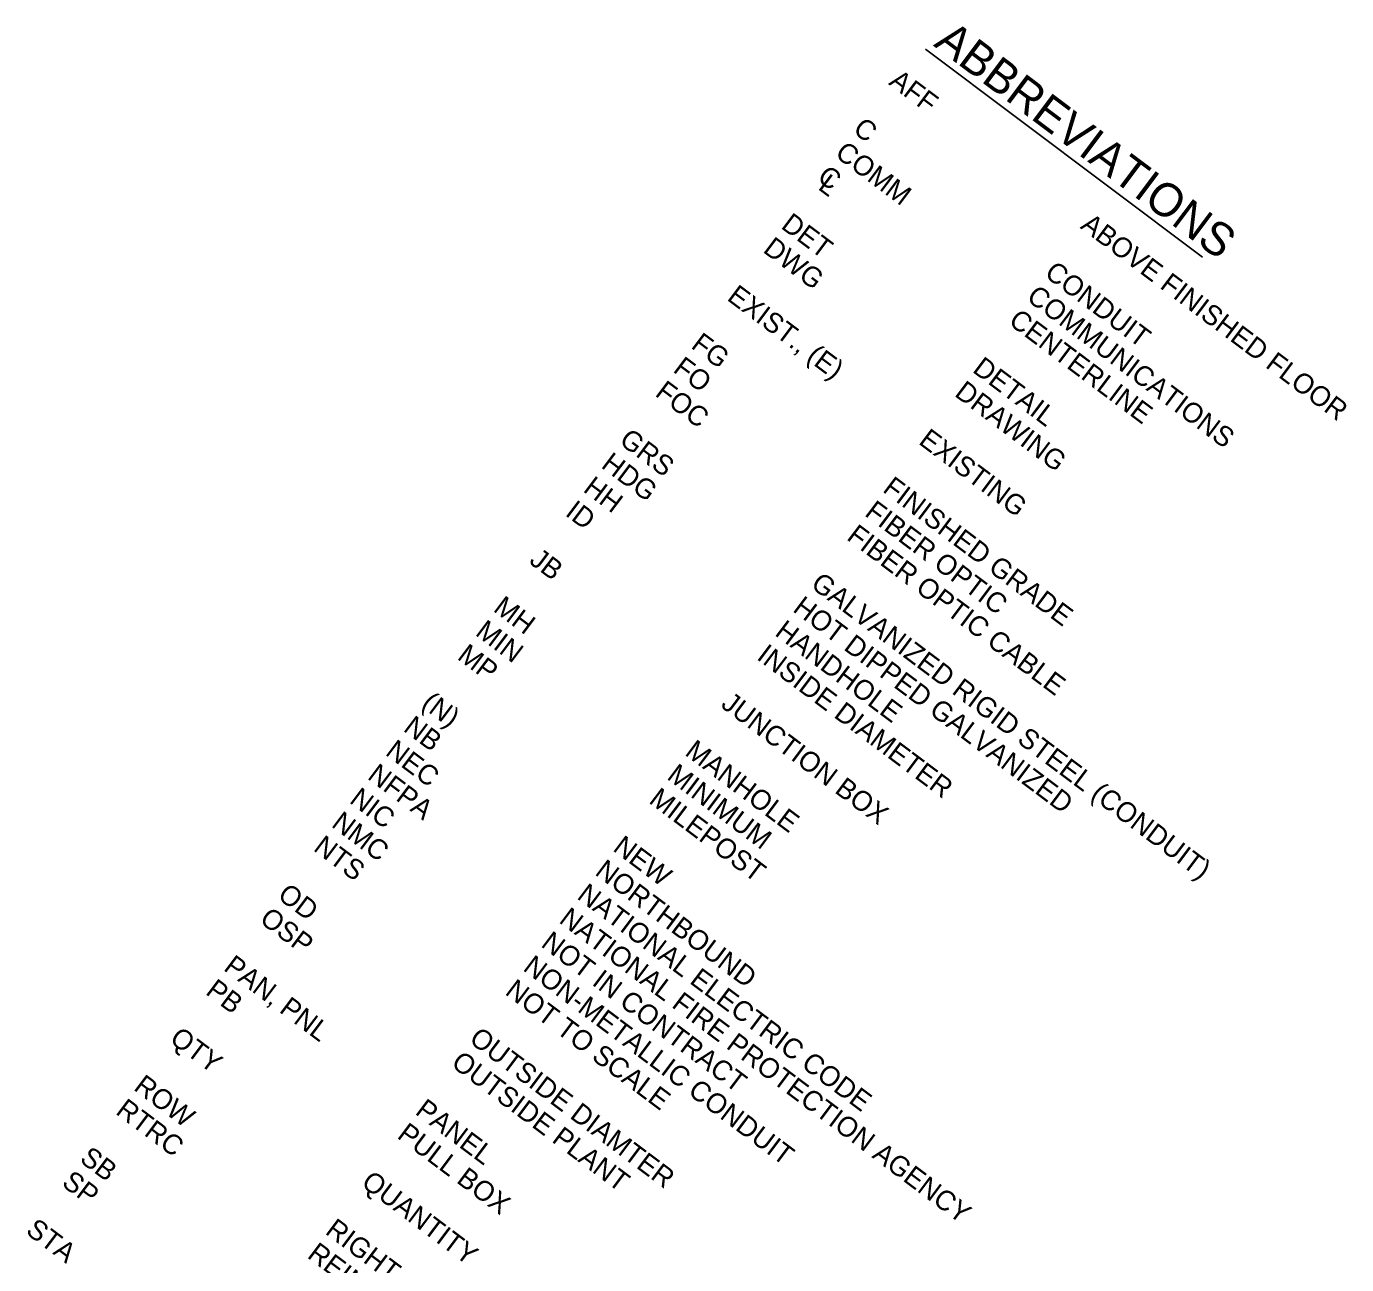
# Model space of a CAD drawing. Extents: x 626494 to 629419, y 365986 to 369334.
# Drawn here: x 628015.6 to 628253.6, y 368612.5 to 368835.9 of the extents above; entities that cross this region are included whole.
import ezdxf

# ---------------------------------------------------------------- set-up
doc = ezdxf.new("R2010")
doc.units = 0
doc.layers.add('R_Shade Frontage Road', color=7, linetype='Continuous')

msp = doc.modelspace()

# ---------------------------------------------------------------- linework, layer by layer
at = {"layer": 'R_Shade Frontage Road'}
msp.add_line((628177.68, 368831.77), (628227.63, 368794.27), dxfattribs=at)

# ---------------------------------------------------------------- texts
for s, height, p in [('ABBREVIATIONS', 6, (628178.99, 368832.47)), ('AFF', 3.6, (628170.89, 368825.52)), ('C', 3.6, (628164.41, 368816.88)), ('COMM', 3.6, (628161.17, 368812.56)), ('L', 3.6, (628158.13, 368806.64)), ('C', 3.6, (628157.95, 368808.23)), ('DET', 3.6, (628151.44, 368799.61)), ('ABOVE FINISHED FLOOR', 3.6, (628205.44, 368799.58)), ('DWG', 3.6, (628148.2, 368795.29)), ('CONDUIT', 3.6, (628198.95, 368790.94)), ('EXIST., (E)', 3.6, (628141.71, 368786.65)), ('COMMUNICATIONS ', 3.6, (628195.71, 368786.62)), ('CENTERLINE', 3.6, (628192.47, 368782.31)), ('FG', 3.6, (628135.23, 368778.02)), ('FO', 3.6, (628131.98, 368773.7)), ('DETAIL', 3.6, (628185.98, 368773.67)), ('FOC', 3.6, (628128.74, 368769.38)), ('DRAWING', 3.6, (628182.74, 368769.35)), ('GRS', 3.6, (628122.26, 368760.75)), ('EXISTING', 3.6, (628176.26, 368760.71)), ('HDG', 3.6, (628119.01, 368756.43)), ('HH', 3.6, (628115.77, 368752.11)), ('FINISHED GRADE', 3.6, (628169.77, 368752.08)), ('ID', 3.6, (628112.53, 368747.79)), ('FIBER OPTIC', 3.6, (628166.53, 368747.76)), ('FIBER OPTIC CABLE', 3.6, (628163.29, 368743.44)), ('JB', 3.6, (628106.04, 368739.16)), ('GALVANIZED RIGID STEEL (CONDUIT)', 3.6, (628156.8, 368734.81)), ('MH', 3.6, (628099.56, 368730.52)), ('HOT DIPPED GALVANIZED', 3.6, (628153.56, 368730.49)), ('MIN', 3.6, (628096.32, 368726.2)), ('HANDHOLE', 3.6, (628150.32, 368726.17)), ('MP', 3.6, (628093.07, 368721.88)), ('INSIDE DIAMETER', 3.6, (628147.07, 368721.85)), ('(N)', 3.6, (628086.59, 368713.25)), ('JUNCTION BOX', 3.6, (628140.59, 368713.22)), ('NB', 3.6, (628083.35, 368708.93)), ('NEC', 3.6, (628080.1, 368704.61)), ('MANHOLE', 3.6, (628134.1, 368704.58)), ('NFPA', 3.6, (628076.86, 368700.29)), ('MINIMUM', 3.6, (628130.86, 368700.26)), ('NIC', 3.6, (628073.62, 368695.97)), ('MILEPOST', 3.6, (628127.62, 368695.94)), ('NMC', 3.6, (628070.38, 368691.66)), ('NTS', 3.6, (628067.13, 368687.34)), ('NEW', 3.6, (628121.13, 368687.31)), ('NORTHBOUND', 3.6, (628117.89, 368682.99)), ('OD', 3.6, (628060.65, 368678.7)), ('NATIONAL ELECTRIC CODE', 3.6, (628114.65, 368678.67)), ('OSP', 3.6, (628057.41, 368674.38)), ('NATIONAL FIRE PROTECTION AGENCY', 3.6, (628111.41, 368674.35)), ('NOT IN CONTRACT', 3.6, (628108.16, 368670.03)), ('PAN, PNL', 3.6, (628050.92, 368665.75)), ('NON-METALLIC CONDUIT', 3.6, (628104.92, 368665.72)), ('PB', 3.6, (628047.68, 368661.43)), ('NOT TO SCALE', 3.6, (628101.68, 368661.4)), ('QTY', 3.6, (628041.19, 368652.79)), ('OUTSIDE DIAMTER', 3.6, (628095.19, 368652.76)), ('OUTSIDE PLANT', 3.6, (628091.95, 368648.44)), ('ROW', 3.6, (628034.71, 368644.16)), ('RTRC', 3.6, (628031.47, 368639.84)), ('PANEL', 3.6, (628085.47, 368639.81)), ('PULL BOX', 3.6, (628082.22, 368635.49)), ('SB', 3.6, (628024.98, 368631.2)), ('SP', 3.6, (628021.74, 368626.88)), ('QUANTITY', 3.6, (628075.74, 368626.85)), ('STA', 3.6, (628015.25, 368618.25)), ('RIGHT OF WAY', 3.6, (628069.25, 368618.22)), ('REINFORCED THERMOSETTING RESIN CONDUIT', 3.6, (628066.01, 368613.9))]:
    msp.add_text(s, height=height, rotation=323.0968, dxfattribs=at).set_placement(p)

doc.saveas('drawing.dxf')
